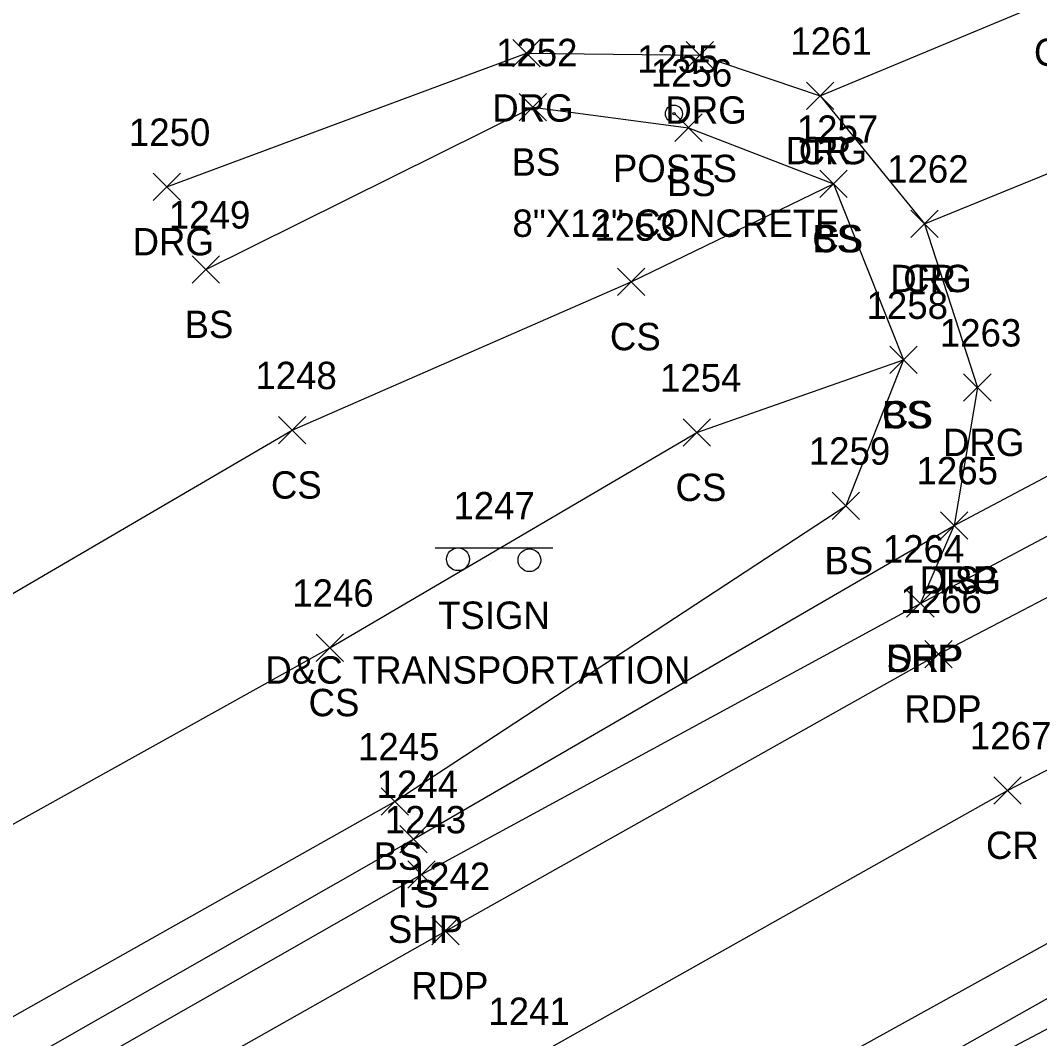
# Model space of a CAD drawing. Extents: x 1606530 to 1613020, y 784959 to 789666.
# Drawn here: x 1608865.5 to 1608940, y 788324.6 to 788399 of the extents above; entities that cross this region are included whole.
import ezdxf

# ---------------------------------------------------------------- set-up
doc = ezdxf.new("R2010")
doc.units = 0
for name, color, linetype in [('L_A', 7, 'Continuous'), ('L_C', 7, 'Continuous'), ('L_I', 7, 'Continuous'), ('L_TIC', 7, 'Continuous'), ('LELB', 7, 'Continuous'), ('LPST', 7, 'Continuous'), ('P_A', 7, 'Continuous'), ('P_I', 7, 'Continuous'), ('P_TIC', 7, 'Continuous'), ('PET', 7, 'Continuous'), ('PRC', 7, 'Continuous'), ('PSP', 7, 'Continuous'), ('R_A', 7, 'Continuous'), ('R_I', 7, 'Continuous'), ('R_TIC', 7, 'Continuous'), ('RDG', 7, 'Continuous'), ('RDP', 7, 'Continuous'), ('S_A', 7, 'Continuous'), ('S_C', 7, 'Continuous'), ('S_I', 7, 'Continuous'), ('SSGN', 7, 'Continuous')]:
    doc.layers.add(name, color=color, linetype=linetype)

msp = doc.modelspace()

# ---------------------------------------------------------------- linework, layer by layer
at = {"layer": 'L_TIC'}
for points in [[(1608901.939, 788391.636), (1608903.939, 788393.636)], [(1608903.939, 788391.636), (1608901.939, 788393.636)], [(1608913.299, 788390.145), (1608915.299, 788392.145)], [(1608915.299, 788390.145), (1608913.299, 788392.145)], [(1608923.911, 788386.038), (1608925.911, 788388.038)], [(1608925.911, 788386.038), (1608923.911, 788388.038)], [(1608923.911, 788386.038), (1608925.911, 788388.038)], [(1608925.911, 788386.038), (1608923.911, 788388.038)], [(1608878.047, 788379.777), (1608880.047, 788381.777)], [(1608880.047, 788379.777), (1608878.047, 788381.777)], [(1608909.124, 788378.884), (1608911.124, 788380.884)], [(1608911.124, 788378.884), (1608909.124, 788380.884)], [(1608929.01, 788373.175), (1608931.01, 788375.175)], [(1608931.01, 788373.175), (1608929.01, 788375.175)], [(1608929.01, 788373.175), (1608931.01, 788375.175)], [(1608931.01, 788373.175), (1608929.01, 788375.175)], [(1608884.358, 788368.044), (1608886.358, 788370.044)], [(1608886.358, 788368.044), (1608884.358, 788370.044)], [(1608913.919, 788367.869), (1608915.919, 788369.869)], [(1608915.919, 788367.869), (1608913.919, 788369.869)], [(1608924.798, 788362.52), (1608926.798, 788364.52)], [(1608926.798, 788362.52), (1608924.798, 788364.52)], [(1608924.798, 788362.52), (1608926.798, 788364.52)], [(1608926.798, 788362.52), (1608924.798, 788364.52)], [(1608932.711, 788361.091), (1608934.711, 788363.091)], [(1608934.711, 788361.091), (1608932.711, 788363.091)], [(1608887.107, 788352.148), (1608889.107, 788354.148)], [(1608889.107, 788352.148), (1608887.107, 788354.148)], [(1608891.854, 788340.929), (1608893.854, 788342.929)], [(1608893.854, 788340.929), (1608891.854, 788342.929)], [(1608893.214, 788338.177), (1608895.214, 788340.177)], [(1608895.214, 788338.177), (1608893.214, 788340.177)]]:
    msp.add_lwpolyline(points, dxfattribs=at)
at = {"layer": 'LELB'}
for points in [[(1608830.696, 788263.063), (1608870.165, 788285.39), (1608903.607, 788303.663), (1608913.174, 788310.86), (1608944.686, 788327.514), (1608982.087, 788348.333), (1609025.652, 788367.839), (1609062.434, 788383.436), (1609080.361, 788388.448), (1609093.562, 788391.85), (1609111.494, 788398.335), (1609124.294, 788403.549), (1609165.327, 788413.887), (1609196.534, 788419.382), (1609241.91, 788424.939), (1609287.826, 788428.62), (1609331.16, 788428.802), (1609379.004, 788428.227), (1609424.692, 788425.716), (1609443.901, 788424.449), (1609475.845, 788418.568), (1609486.477, 788419.986), (1609502.626, 788421.703)], [(1608879.047, 788380.777), (1608902.939, 788392.636), (1608914.299, 788391.145), (1608924.911, 788387.038), (1608930.01, 788374.175), (1608925.798, 788363.52)], [(1608794.851, 788319.6), (1608842.242, 788343.871), (1608885.358, 788369.044), (1608910.124, 788379.884), (1608924.911, 788387.038)], [(1608803.649, 788305.105), (1608847.823, 788330.73), (1608888.107, 788353.148), (1608914.919, 788368.869), (1608930.01, 788374.175)], [(1608809.636, 788293.729), (1608853.125, 788319.567), (1608892.854, 788341.929), (1608925.798, 788363.52)], [(1608811.684, 788290.669), (1608854.482, 788316.493), (1608894.214, 788339.177), (1608933.711, 788362.091)]]:
    msp.add_lwpolyline(points, dxfattribs=at)
at = {"layer": 'LPST'}
for radius in [0.625, 0.0833]:
    msp.add_circle((1608913.242, 788392.167), radius, dxfattribs=at)
at = {"layer": 'P_TIC'}
for points in [[(1608922.922, 788392.468), (1608924.922, 788394.468)], [(1608924.922, 788392.468), (1608922.922, 788394.468)], [(1608930.56, 788383.128), (1608932.56, 788385.128)], [(1608932.56, 788383.128), (1608930.56, 788385.128)], [(1608930.247, 788355.378), (1608932.247, 788357.378)], [(1608932.247, 788355.378), (1608930.247, 788357.378)], [(1608931.583, 788351.682), (1608933.583, 788353.682)], [(1608933.583, 788351.682), (1608931.583, 788353.682)], [(1608936.609, 788341.722), (1608938.609, 788343.722)], [(1608938.609, 788341.722), (1608936.609, 788343.722)], [(1608893.808, 788335.591), (1608895.808, 788337.591)], [(1608895.808, 788335.591), (1608893.808, 788337.591)], [(1608895.559, 788331.458), (1608897.559, 788333.458)], [(1608897.559, 788331.458), (1608895.559, 788333.458)]]:
    msp.add_lwpolyline(points, dxfattribs=at)
at = {"layer": 'PET'}
for points in [[(1608827.199, 788266.245), (1608867.859, 788290.541), (1608906.681, 788312.856), (1608942.677, 788332.755), (1608980.541, 788352.164), (1609023.571, 788373.225), (1609061.437, 788389.904), (1609090.798, 788401.175), (1609121.915, 788410.089), (1609165.169, 788419.998), (1609195.853, 788425.54), (1609240.139, 788431.13), (1609287.877, 788434.372), (1609331.481, 788435.115), (1609378.889, 788434.051), (1609425.427, 788432.251), (1609443.83, 788431.331), (1609477.321, 788429.782), (1609518.441, 788427.602), (1609569.185, 788424.684), (1609602.993, 788422.58), (1609641.45, 788420.372), (1609681.697, 788417.919), (1609727.381, 788415.531)], [(1608858.102, 788310.732), (1608896.559, 788332.458), (1608932.583, 788352.682), (1608960.396, 788367.207), (1608987.919, 788381.261), (1609019.358, 788396.212), (1609040.554, 788405.359), (1609066.482, 788415.581), (1609102.049, 788427.759), (1609127.707, 788434.803)]]:
    msp.add_lwpolyline(points, dxfattribs=at)
at = {"layer": 'PRC'}
for points in [[(1608863.252, 788300.903), (1608901.811, 788322.596), (1608937.609, 788342.722), (1608976.118, 788362.757), (1609017.577, 788382.951), (1609062.579, 788402.235), (1609089.789, 788412.891), (1609118.805, 788421.444), (1609162.845, 788431.752), (1609194.146, 788437.356), (1609237.64, 788442.85), (1609286.897, 788446.16), (1609332.711, 788446.436), (1609379.393, 788445.342), (1609425.621, 788443.432), (1609445.831, 788442.47), (1609477.779, 788440.947), (1609519.757, 788438.847), (1609569.723, 788435.898), (1609601.73, 788434.311), (1609642.39, 788431.817), (1609682.025, 788429.153), (1609726.546, 788426.785)], [(1608923.922, 788393.468), (1608941.111, 788400.66), (1608953.393, 788406.216)], [(1608931.56, 788384.128), (1608947.211, 788390.504), (1608959.617, 788395.349)]]:
    msp.add_lwpolyline(points, dxfattribs=at)
at = {"layer": 'PSP'}
for points in [[(1608855.389, 788314.113), (1608894.808, 788336.591), (1608931.247, 788356.378), (1608958.599, 788370.933), (1608985.981, 788385.272), (1609018.034, 788400.244), (1609039.035, 788409.707), (1609065.41, 788420.262), (1609085.948, 788428.615), (1609114.118, 788436.455)], [(1608830.356, 788264.996), (1608869.22, 788287.395), (1608908.593, 788309.539), (1608943.858, 788329.41), (1608981.495, 788349.27), (1609025.121, 788370.206), (1609061.921, 788386.228), (1609076.386, 788391.443), (1609089.956, 788397.157), (1609122.924, 788407.129), (1609165.713, 788417.027), (1609196.423, 788422.444), (1609241.306, 788428.683), (1609287.876, 788431.577), (1609331.197, 788431.668), (1609378.916, 788430.276), (1609425.006, 788428.307)]]:
    msp.add_lwpolyline(points, dxfattribs=at)
at = {"layer": 'R_TIC'}
for points in [[(1608901.481, 788395.582), (1608903.481, 788397.582)], [(1608903.481, 788395.582), (1608901.481, 788397.582)], [(1608914.131, 788395.434), (1608916.131, 788397.434)], [(1608916.131, 788395.434), (1608914.131, 788397.434)], [(1608922.922, 788392.468), (1608924.922, 788394.468)], [(1608924.922, 788392.468), (1608922.922, 788394.468)], [(1608875.204, 788385.815), (1608877.204, 788387.815)], [(1608877.204, 788385.815), (1608875.204, 788387.815)], [(1608930.56, 788383.128), (1608932.56, 788385.128)], [(1608932.56, 788383.128), (1608930.56, 788385.128)], [(1608934.412, 788371.158), (1608936.412, 788373.158)], [(1608936.412, 788371.158), (1608934.412, 788373.158)], [(1608932.711, 788361.091), (1608934.711, 788363.091)], [(1608934.711, 788361.091), (1608932.711, 788363.091)], [(1608932.711, 788361.091), (1608934.711, 788363.091)], [(1608934.711, 788361.091), (1608932.711, 788363.091)], [(1608930.247, 788355.378), (1608932.247, 788357.378)], [(1608932.247, 788355.378), (1608930.247, 788357.378)]]:
    msp.add_lwpolyline(points, dxfattribs=at)
at = {"layer": 'RDG'}
msp.add_lwpolyline([(1608876.204, 788386.815), (1608902.481, 788396.582), (1608915.131, 788396.434), (1608923.922, 788393.468), (1608931.56, 788384.128), (1608935.412, 788372.158), (1608933.711, 788362.091)], dxfattribs=at)
at = {"layer": 'RDP'}
msp.add_lwpolyline([(1608931.247, 788356.378), (1608933.711, 788362.091), (1608956.476, 788374.132), (1608977.618, 788385.058), (1608985.981, 788385.272)], dxfattribs=at)
at = {"layer": 'SSGN'}
for p, q in [((1608895.81, 788360.449), (1608904.407, 788360.449)), ((1608899.832, 788359.545), (1608899.832, 788359.545))]:
    msp.add_line(p, q, dxfattribs=at)
for centre in [(1608897.471, 788359.616), (1608902.686, 788359.546)]:
    msp.add_circle(centre, 0.833, dxfattribs=at)

# ---------------------------------------------------------------- texts
at = {"layer": 'L_A'}
for s, p in [('BS', (1608901.38, 788387.636)), ('POSTS', (1608908.785, 788387.167)), ('BS', (1608912.74, 788386.145)), ('CS', (1608923.352, 788382.038)), ('BS', (1608923.352, 788382.038)), ('BS', (1608877.488, 788375.777)), ('CS', (1608908.565, 788374.884)), ('CS', (1608928.451, 788369.175)), ('BS', (1608928.451, 788369.175)), ('CS', (1608883.799, 788364.044)), ('CS', (1608913.36, 788363.869)), ('BS', (1608924.239, 788358.52)), ('BS', (1608924.239, 788358.52)), ('TS', (1608932.121, 788357.091)), ('CS', (1608886.548, 788348.148)), ('BS', (1608891.295, 788336.929)), ('TS', (1608892.623, 788334.177))]:
    msp.add_text(s, height=2, dxfattribs=at).set_placement(p)
at = {"layer": 'L_C'}
msp.add_text('8"X12" CONCRETE', height=2, dxfattribs=at).set_placement((1608901.447, 788383.167))
at = {"layer": 'L_I'}
for s, p in [('1252', (1608900.246, 788395.636)), ('1255', (1608910.549, 788395.167)), ('1256', (1608911.551, 788394.145)), ('1257', (1608922.218, 788390.038)), ('1257', (1608922.218, 788390.038)), ('1249', (1608876.347, 788383.777)), ('1253', (1608907.432, 788382.884)), ('1258', (1608927.317, 788377.175)), ('1258', (1608927.317, 788377.175)), ('1248', (1608882.665, 788372.044)), ('1254', (1608912.226, 788371.869)), ('1259', (1608923.098, 788366.52)), ('1259', (1608923.098, 788366.52)), ('1265', (1608930.971, 788365.091)), ('1246', (1608885.36, 788356.148)), ('1245', (1608890.162, 788344.929)), ('1244', (1608891.521, 788342.177))]:
    msp.add_text(s, height=2, dxfattribs=at).set_placement(p)
at = {"layer": 'P_A'}
for s, p in [('CR', (1608939.544, 788395.66)), ('CR', (1608922.355, 788388.468)), ('CR', (1608929.993, 788379.128)), ('SHP', (1608928.783, 788351.378)), ('RDP', (1608930.071, 788347.682)), ('CR', (1608936.042, 788337.722)), ('SHP', (1608892.343, 788331.591)), ('RDP', (1608894.048, 788327.458))]:
    msp.add_text(s, height=2, dxfattribs=at).set_placement(p)
at = {"layer": 'P_I'}
for s, p in [('1261', (1608921.749, 788396.468)), ('1262', (1608928.82, 788387.128)), ('1264', (1608928.507, 788359.378)), ('1266', (1608929.788, 788355.682)), ('1267', (1608934.869, 788345.722)), ('1243', (1608892.115, 788339.591)), ('1242', (1608893.867, 788335.458)), ('1241', (1608899.685, 788325.596))]:
    msp.add_text(s, height=2, dxfattribs=at).set_placement(p)
at = {"layer": 'R_A'}
for s, p in [('DRG', (1608899.969, 788391.582)), ('DRG', (1608912.619, 788391.434)), ('DRG', (1608921.41, 788388.468)), ('DRG', (1608873.693, 788381.815)), ('DRG', (1608929.048, 788379.128)), ('DRG', (1608932.9, 788367.158)), ('DRG', (1608931.2, 788357.091)), ('DRP', (1608931.2, 788357.091)), ('DRP', (1608928.736, 788351.378))]:
    msp.add_text(s, height=2, dxfattribs=at).set_placement(p)
at = {"layer": 'R_I'}
for s, p in [('1261', (1608921.749, 788396.468)), ('1250', (1608873.425, 788389.815)), ('1262', (1608928.82, 788387.128)), ('1263', (1608932.672, 788375.158)), ('1265', (1608930.971, 788365.091)), ('1265', (1608930.971, 788365.091)), ('1264', (1608928.507, 788359.378))]:
    msp.add_text(s, height=2, dxfattribs=at).set_placement(p)
at = {"layer": 'S_A'}
msp.add_text('TSIGN', height=2, dxfattribs=at).set_placement((1608896.008, 788354.528))
at = {"layer": 'S_C'}
msp.add_text('D&C TRANSPORTATION', height=2, dxfattribs=at).set_placement((1608883.394, 788350.528))
at = {"layer": 'S_I'}
msp.add_text('1247', height=2, dxfattribs=at).set_placement((1608897.134, 788362.528))

doc.saveas('drawing.dxf')
